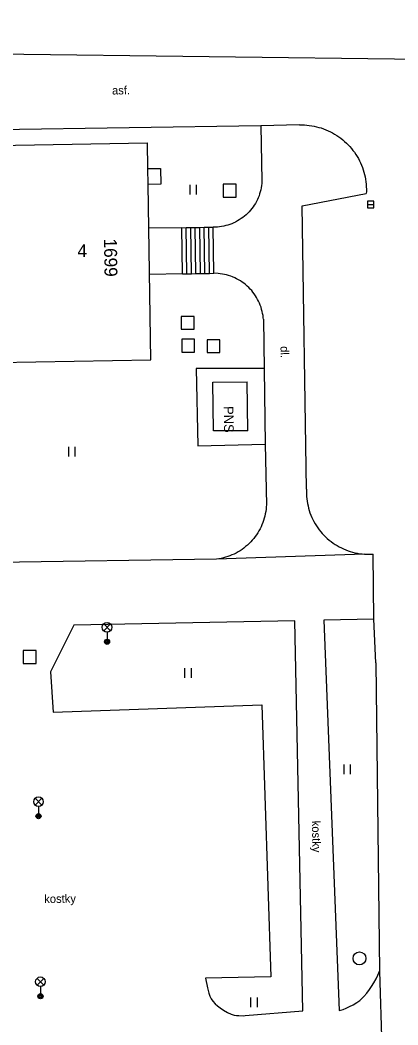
# Model space of a CAD drawing. Extents: x -641829 to -641525, y -1114855 to -1114359.
# Drawn here: x -641611.8 to -641582.5, y -1114437 to -1114358.9 of the extents above; entities that cross this region are included whole.
import ezdxf

# ---------------------------------------------------------------- set-up
doc = ezdxf.new("R2010")
doc.units = 0
for name, color, linetype in [('Vrstva 1', 7, 'Continuous'), ('Vrstva 10', 7, 'Continuous'), ('Vrstva 11', 7, 'Continuous'), ('Vrstva 24', 7, 'Continuous'), ('Vrstva 26', 7, 'Continuous'), ('Vrstva 27', 7, 'Continuous'), ('Vrstva 33', 7, 'Continuous'), ('Vrstva 36', 7, 'Continuous'), ('Vrstva 40', 7, 'Continuous'), ('Vrstva 41', 7, 'Continuous'), ('Vrstva 46', 7, 'Continuous'), ('Vrstva 47', 7, 'Continuous'), ('Vrstva 5', 7, 'Continuous')]:
    doc.layers.add(name, color=color, linetype=linetype)

msp = doc.modelspace()

# ---------------------------------------------------------------- linework, layer by layer
at = {"layer": 'Vrstva 1'}
msp.add_line((-641525.3, -1114362.64), (-641828.67, -1114358.89), dxfattribs=at)
at = {"layer": 'Vrstva 10'}
for p, q in [((-641593.11, -1114367.12), (-641618.09, -1114367.49)), ((-641590.1, -1114367.04), (-641593.11, -1114367.12)), ((-641590.1, -1114367.04), (-641589.91, -1114367.04)), ((-641589.91, -1114367.04), (-641589.72, -1114367.04)), ((-641589.72, -1114367.04), (-641589.53, -1114367.06)), ((-641589.53, -1114367.06), (-641589.34, -1114367.08)), ((-641589.34, -1114367.08), (-641589.15, -1114367.11)), ((-641589.15, -1114367.11), (-641588.96, -1114367.14)), ((-641588.96, -1114367.14), (-641588.78, -1114367.18)), ((-641588.78, -1114367.18), (-641588.59, -1114367.23)), ((-641588.59, -1114367.23), (-641588.41, -1114367.28)), ((-641588.41, -1114367.28), (-641588.23, -1114367.35)), ((-641588.23, -1114367.35), (-641588.05, -1114367.42)), ((-641588.05, -1114367.42), (-641587.87, -1114367.49)), ((-641587.87, -1114367.49), (-641587.7, -1114367.57)), ((-641587.7, -1114367.57), (-641587.53, -1114367.66)), ((-641587.53, -1114367.66), (-641587.37, -1114367.76)), ((-641587.37, -1114367.76), (-641587.2, -1114367.86)), ((-641587.2, -1114367.86), (-641587.05, -1114367.97)), ((-641587.05, -1114367.97), (-641586.89, -1114368.08)), ((-641586.89, -1114368.08), (-641586.74, -1114368.2)), ((-641586.74, -1114368.2), (-641586.6, -1114368.32)), ((-641586.6, -1114368.32), (-641586.46, -1114368.45)), ((-641586.46, -1114368.45), (-641586.32, -1114368.59)), ((-641586.32, -1114368.59), (-641586.19, -1114368.73)), ((-641586.19, -1114368.73), (-641586.07, -1114368.87)), ((-641586.07, -1114368.87), (-641585.95, -1114369.02)), ((-641585.95, -1114369.02), (-641585.84, -1114369.17)), ((-641585.84, -1114369.17), (-641585.73, -1114369.33)), ((-641585.73, -1114369.33), (-641585.63, -1114369.49)), ((-641585.63, -1114369.49), (-641585.53, -1114369.66)), ((-641585.53, -1114369.66), (-641585.44, -1114369.83)), ((-641585.44, -1114369.83), (-641585.36, -1114370)), ((-641585.36, -1114370), (-641585.28, -1114370.18)), ((-641585.28, -1114370.18), (-641585.21, -1114370.35)), ((-641585.21, -1114370.35), (-641585.15, -1114370.53)), ((-641585.15, -1114370.53), (-641585.1, -1114370.72)), ((-641585.1, -1114370.72), (-641585.05, -1114370.9)), ((-641585.05, -1114370.9), (-641585.01, -1114371.09)), ((-641585.01, -1114371.09), (-641584.97, -1114371.27)), ((-641584.97, -1114371.27), (-641584.94, -1114371.46)), ((-641584.94, -1114371.46), (-641584.92, -1114371.65)), ((-641584.92, -1114371.65), (-641584.91, -1114371.85)), ((-641584.91, -1114371.85), (-641584.9, -1114372.04)), ((-641584.9, -1114372.04), (-641584.9, -1114372.23)), ((-641589.89, -1114373.33), (-641584.91, -1114372.38)), ((-641584.9, -1114372.23), (-641584.91, -1114372.38)), ((-641589.57, -1114395.37), (-641589.89, -1114373.33)), ((-641589.57, -1114395.37), (-641589.57, -1114395.56)), ((-641589.57, -1114395.56), (-641589.57, -1114395.74)), ((-641589.57, -1114395.74), (-641589.56, -1114395.93)), ((-641589.56, -1114395.93), (-641589.54, -1114396.12)), ((-641589.54, -1114396.12), (-641589.52, -1114396.3)), ((-641589.52, -1114396.3), (-641589.49, -1114396.49)), ((-641589.49, -1114396.49), (-641589.44, -1114396.67)), ((-641589.44, -1114396.67), (-641589.4, -1114396.85)), ((-641589.4, -1114396.85), (-641589.35, -1114397.03)), ((-641589.35, -1114397.03), (-641589.29, -1114397.21)), ((-641589.29, -1114397.21), (-641589.22, -1114397.38)), ((-641589.22, -1114397.38), (-641589.15, -1114397.56)), ((-641589.15, -1114397.56), (-641589.07, -1114397.73)), ((-641589.07, -1114397.73), (-641588.98, -1114397.89)), ((-641588.98, -1114397.89), (-641588.89, -1114398.05)), ((-641588.89, -1114398.05), (-641588.79, -1114398.21)), ((-641588.79, -1114398.21), (-641588.68, -1114398.37)), ((-641588.68, -1114398.37), (-641588.57, -1114398.52)), ((-641588.57, -1114398.52), (-641588.45, -1114398.67)), ((-641588.45, -1114398.67), (-641588.33, -1114398.81)), ((-641588.33, -1114398.81), (-641588.2, -1114398.95)), ((-641588.2, -1114398.95), (-641588.07, -1114399.08)), ((-641588.07, -1114399.08), (-641587.94, -1114399.2)), ((-641587.94, -1114399.2), (-641587.79, -1114399.33)), ((-641587.79, -1114399.33), (-641587.65, -1114399.44)), ((-641587.65, -1114399.44), (-641587.49, -1114399.55)), ((-641587.49, -1114399.55), (-641587.34, -1114399.66)), ((-641587.34, -1114399.66), (-641587.18, -1114399.75)), ((-641587.18, -1114399.75), (-641587.02, -1114399.85)), ((-641587.02, -1114399.85), (-641586.85, -1114399.93)), ((-641586.85, -1114399.93), (-641586.68, -1114400.01)), ((-641586.68, -1114400.01), (-641586.51, -1114400.08)), ((-641586.51, -1114400.08), (-641586.33, -1114400.15)), ((-641586.33, -1114400.15), (-641586.16, -1114400.21)), ((-641586.16, -1114400.21), (-641585.98, -1114400.26)), ((-641585.98, -1114400.26), (-641585.79, -1114400.31)), ((-641585.79, -1114400.31), (-641585.61, -1114400.35)), ((-641585.61, -1114400.35), (-641585.43, -1114400.38)), ((-641585.43, -1114400.38), (-641585.24, -1114400.4)), ((-641585.24, -1114400.4), (-641585.05, -1114400.42)), ((-641585.05, -1114400.42), (-641584.87, -1114400.43)), ((-641584.87, -1114400.43), (-641584.68, -1114400.43)), ((-641584.68, -1114400.43), (-641584.49, -1114400.43)), ((-641584.49, -1114400.43), (-641584.39, -1114400.42)), ((-641584.33, -1114405.48), (-641584.39, -1114400.42)), ((-641584.18, -1114408.87), (-641584.33, -1114405.48)), ((-641584.18, -1114408.87), (-641583.89, -1114432.83)), ((-641583.89, -1114432.83), (-641583.53, -1114444.1))]:
    msp.add_line(p, q, dxfattribs=at)
at = {"layer": 'Vrstva 11'}
for p, q in [((-641593.11, -1114367.12), (-641593.02, -1114371.39)), ((-641593.11, -1114372.08), (-641593.15, -1114372.24)), ((-641593.08, -1114371.92), (-641593.11, -1114372.08)), ((-641593.05, -1114371.76), (-641593.08, -1114371.92)), ((-641593.03, -1114371.59), (-641593.05, -1114371.76)), ((-641593.02, -1114371.39), (-641593.03, -1114371.59)), ((-641593.38, -1114372.85), (-641593.45, -1114373)), ((-641593.31, -1114372.7), (-641593.38, -1114372.85)), ((-641593.25, -1114372.55), (-641593.31, -1114372.7)), ((-641593.2, -1114372.4), (-641593.25, -1114372.55)), ((-641593.15, -1114372.24), (-641593.2, -1114372.4)), ((-641593.81, -1114373.55), (-641593.91, -1114373.68)), ((-641593.71, -1114373.42), (-641593.81, -1114373.55)), ((-641593.62, -1114373.28), (-641593.71, -1114373.42)), ((-641593.53, -1114373.14), (-641593.62, -1114373.28)), ((-641593.45, -1114373), (-641593.53, -1114373.14)), ((-641594.78, -1114374.42), (-641594.92, -1114374.51)), ((-641594.64, -1114374.33), (-641594.78, -1114374.42)), ((-641594.51, -1114374.24), (-641594.64, -1114374.33)), ((-641594.38, -1114374.14), (-641594.51, -1114374.24)), ((-641594.26, -1114374.03), (-641594.38, -1114374.14)), ((-641594.14, -1114373.92), (-641594.26, -1114374.03)), ((-641594.02, -1114373.8), (-641594.14, -1114373.92)), ((-641593.91, -1114373.68), (-641594.02, -1114373.8)), ((-641599.26, -1114375.03), (-641601.82, -1114375.07)), ((-641599.26, -1114375.03), (-641598.91, -1114375.02)), ((-641599.2, -1114378.62), (-641599.26, -1114375.03)), ((-641598.85, -1114378.61), (-641598.91, -1114375.02)), ((-641598.91, -1114375.02), (-641598.56, -1114375.02)), ((-641598.56, -1114375.02), (-641598.21, -1114375.01)), ((-641598.5, -1114378.61), (-641598.56, -1114375.02)), ((-641598.15, -1114378.6), (-641598.21, -1114375.01)), ((-641598.21, -1114375.01), (-641597.86, -1114375.01)), ((-641597.86, -1114375.01), (-641597.51, -1114375)), ((-641597.8, -1114378.6), (-641597.86, -1114375.01)), ((-641597.45, -1114378.59), (-641597.51, -1114375)), ((-641597.51, -1114375), (-641597.16, -1114375)), ((-641597.16, -1114375), (-641596.81, -1114374.99)), ((-641597.1, -1114378.59), (-641597.16, -1114375)), ((-641596.48, -1114374.98), (-641596.81, -1114374.99)), ((-641596.76, -1114378.58), (-641596.81, -1114374.99)), ((-641596.32, -1114374.96), (-641596.48, -1114374.98)), ((-641596.16, -1114374.94), (-641596.32, -1114374.96)), ((-641595.99, -1114374.91), (-641596.16, -1114374.94)), ((-641595.84, -1114374.87), (-641595.99, -1114374.91)), ((-641595.68, -1114374.83), (-641595.84, -1114374.87)), ((-641595.52, -1114374.78), (-641595.68, -1114374.83)), ((-641595.37, -1114374.72), (-641595.52, -1114374.78)), ((-641595.22, -1114374.66), (-641595.37, -1114374.72)), ((-641595.07, -1114374.59), (-641595.22, -1114374.66)), ((-641594.92, -1114374.51), (-641595.07, -1114374.59)), ((-641599.2, -1114378.62), (-641601.76, -1114378.66)), ((-641599.2, -1114378.62), (-641598.85, -1114378.61)), ((-641598.85, -1114378.61), (-641598.5, -1114378.61)), ((-641598.5, -1114378.61), (-641598.15, -1114378.6)), ((-641598.15, -1114378.6), (-641597.8, -1114378.6)), ((-641597.8, -1114378.6), (-641597.45, -1114378.59)), ((-641597.45, -1114378.59), (-641597.1, -1114378.59)), ((-641597.1, -1114378.59), (-641596.76, -1114378.58)), ((-641596.42, -1114378.59), (-641596.76, -1114378.58)), ((-641596.26, -1114378.61), (-641596.42, -1114378.59)), ((-641596.09, -1114378.64), (-641596.26, -1114378.61)), ((-641595.93, -1114378.67), (-641596.09, -1114378.64)), ((-641595.77, -1114378.71), (-641595.93, -1114378.67)), ((-641595.61, -1114378.75), (-641595.77, -1114378.71)), ((-641595.45, -1114378.8), (-641595.61, -1114378.75)), ((-641595.3, -1114378.86), (-641595.45, -1114378.8)), ((-641595.14, -1114378.93), (-641595.3, -1114378.86)), ((-641594.99, -1114379), (-641595.14, -1114378.93)), ((-641594.85, -1114379.08), (-641594.99, -1114379)), ((-641594.7, -1114379.17), (-641594.85, -1114379.08)), ((-641594.56, -1114379.26), (-641594.7, -1114379.17)), ((-641594.43, -1114379.35), (-641594.56, -1114379.26)), ((-641594.3, -1114379.46), (-641594.43, -1114379.35)), ((-641594.17, -1114379.57), (-641594.3, -1114379.46)), ((-641594.05, -1114379.68), (-641594.17, -1114379.57)), ((-641593.94, -1114379.8), (-641594.05, -1114379.68)), ((-641593.82, -1114379.92), (-641593.94, -1114379.8)), ((-641593.72, -1114380.05), (-641593.82, -1114379.92)), ((-641593.62, -1114380.18), (-641593.72, -1114380.05)), ((-641593.53, -1114380.32), (-641593.62, -1114380.18)), ((-641593.44, -1114380.46), (-641593.53, -1114380.32)), ((-641593.36, -1114380.61), (-641593.44, -1114380.46)), ((-641593.28, -1114380.75), (-641593.36, -1114380.61)), ((-641593.21, -1114380.91), (-641593.28, -1114380.75)), ((-641593.15, -1114381.06), (-641593.21, -1114380.91)), ((-641593.09, -1114381.22), (-641593.15, -1114381.06)), ((-641593.05, -1114381.38), (-641593.09, -1114381.22)), ((-641593, -1114381.54), (-641593.05, -1114381.38)), ((-641592.97, -1114381.7), (-641593, -1114381.54)), ((-641592.94, -1114381.86), (-641592.97, -1114381.7)), ((-641592.92, -1114382.03), (-641592.94, -1114381.86)), ((-641592.91, -1114382.14), (-641592.92, -1114382.03)), ((-641598.13, -1114385.98), (-641598, -1114392)), ((-641592.85, -1114385.99), (-641598.13, -1114385.98)), ((-641598, -1114392), (-641592.76, -1114391.86)), ((-641592.7, -1114396.92), (-641592.73, -1114397.1)), ((-641592.69, -1114396.74), (-641592.7, -1114396.92)), ((-641592.68, -1114396.59), (-641592.69, -1114396.74)), ((-641592.9, -1114397.79), (-641592.95, -1114397.96)), ((-641592.84, -1114397.62), (-641592.9, -1114397.79)), ((-641592.8, -1114397.45), (-641592.84, -1114397.62)), ((-641592.76, -1114397.27), (-641592.8, -1114397.45)), ((-641592.73, -1114397.1), (-641592.76, -1114397.27)), ((-641593.26, -1114398.61), (-641593.35, -1114398.76)), ((-641593.17, -1114398.45), (-641593.26, -1114398.61)), ((-641593.09, -1114398.29), (-641593.17, -1114398.45)), ((-641593.02, -1114398.13), (-641593.09, -1114398.29)), ((-641592.95, -1114397.96), (-641593.02, -1114398.13)), ((-641593.77, -1114399.33), (-641593.89, -1114399.46)), ((-641593.66, -1114399.2), (-641593.77, -1114399.33)), ((-641593.55, -1114399.05), (-641593.66, -1114399.2)), ((-641593.45, -1114398.91), (-641593.55, -1114399.05)), ((-641593.35, -1114398.76), (-641593.45, -1114398.91)), ((-641594.72, -1114400.15), (-641594.87, -1114400.24)), ((-641594.57, -1114400.05), (-641594.72, -1114400.15)), ((-641594.43, -1114399.94), (-641594.57, -1114400.05)), ((-641594.29, -1114399.83), (-641594.43, -1114399.94)), ((-641594.15, -1114399.71), (-641594.29, -1114399.83)), ((-641594.02, -1114399.59), (-641594.15, -1114399.71)), ((-641593.89, -1114399.46), (-641594.02, -1114399.59)), ((-641596.55, -1114400.81), (-641616.13, -1114401.11)), ((-641585.05, -1114400.42), (-641596.55, -1114400.81)), ((-641596.37, -1114400.78), (-641596.55, -1114400.81)), ((-641596.2, -1114400.75), (-641596.37, -1114400.78)), ((-641596.02, -1114400.71), (-641596.2, -1114400.75)), ((-641595.85, -1114400.66), (-641596.02, -1114400.71)), ((-641595.68, -1114400.61), (-641595.85, -1114400.66)), ((-641595.51, -1114400.55), (-641595.68, -1114400.61)), ((-641595.35, -1114400.48), (-641595.51, -1114400.55)), ((-641595.19, -1114400.41), (-641595.35, -1114400.48)), ((-641595.03, -1114400.33), (-641595.19, -1114400.41)), ((-641594.87, -1114400.24), (-641595.03, -1114400.33)), ((-641590.47, -1114405.6), (-641607.64, -1114405.93)), ((-641589.84, -1114435.92), (-641590.47, -1114405.6)), ((-641584.33, -1114405.48), (-641588.2, -1114405.56)), ((-641588.2, -1114405.56), (-641587.01, -1114435.89)), ((-641607.64, -1114405.93), (-641609.45, -1114409.57)), ((-641609.45, -1114409.57), (-641609.26, -1114412.71)), ((-641609.26, -1114412.71), (-641593.04, -1114412.14)), ((-641593.04, -1114412.14), (-641592.34, -1114433.27)), ((-641592.34, -1114433.27), (-641597.42, -1114433.38))]:
    msp.add_line(p, q, dxfattribs=at)
for points in [[(-641592.91, -1114382.14), (-641592.76, -1114391.86), (-641592.68, -1114396.59)], [(-641585.28, -1114435), (-641585.09, -1114434.81), (-641584.87, -1114434.55), (-641584.66, -1114434.28), (-641584.5, -1114434.03), (-641584.32, -1114433.75), (-641584.15, -1114433.43), (-641584.01, -1114433.15), (-641583.89, -1114432.83)], [(-641597.42, -1114433.38), (-641597.25, -1114434.13), (-641597.15, -1114434.56), (-641597.06, -1114434.78), (-641596.96, -1114434.99)], [(-641596.96, -1114434.99), (-641596.83, -1114435.18), (-641596.67, -1114435.38), (-641596.47, -1114435.55), (-641596.27, -1114435.69), (-641596, -1114435.88), (-641595.7, -1114436.05), (-641595.41, -1114436.19), (-641595.18, -1114436.26)], [(-641587.01, -1114435.89), (-641586.7, -1114435.81), (-641586.47, -1114435.73), (-641586.21, -1114435.6), (-641585.93, -1114435.46), (-641585.65, -1114435.28), (-641585.42, -1114435.12), (-641585.28, -1114435)], [(-641595.18, -1114436.26), (-641594.99, -1114436.3), (-641594.82, -1114436.3), (-641594.45, -1114436.31), (-641594.33, -1114436.3), (-641589.84, -1114435.92)]]:
    msp.add_lwpolyline(points, dxfattribs=at)
at = {"layer": 'Vrstva 24'}
msp.add_lwpolyline([(-641601.89, -1114370.44), (-641600.91, -1114370.42), (-641600.89, -1114371.66), (-641601.87, -1114371.68), (-641601.89, -1114370.44)], dxfattribs=at)
at = {"layer": 'Vrstva 26'}
for points in [[(-641595.03, -1114371.66), (-641596.03, -1114371.66), (-641596.03, -1114372.66), (-641595.03, -1114372.66)], [(-641598.3, -1114381.93), (-641599.3, -1114381.93), (-641599.3, -1114382.93), (-641598.3, -1114382.93)], [(-641598.26, -1114383.71), (-641599.26, -1114383.71), (-641599.26, -1114384.71), (-641598.26, -1114384.71)], [(-641596.29, -1114383.74), (-641597.29, -1114383.74), (-641597.29, -1114384.74), (-641596.29, -1114384.74)], [(-641610.58, -1114407.92), (-641611.58, -1114407.92), (-641611.58, -1114408.92), (-641610.58, -1114408.92)]]:
    msp.add_lwpolyline(points, close=True, dxfattribs=at)
at = {"layer": 'Vrstva 27'}
msp.add_line((-641584.82, -1114373.23), (-641584.32, -1114373.23), dxfattribs=at)
msp.add_lwpolyline([(-641584.82, -1114373.48), (-641584.32, -1114373.48), (-641584.32, -1114372.98), (-641584.82, -1114372.98)], close=True, dxfattribs=at)
msp.add_circle((-641585.44, -1114431.85), 0.5, dxfattribs=at)
at = {"layer": 'Vrstva 33'}
for p, q in [((-641605.324, -1114406.37), (-641604.796, -1114405.84)), ((-641605.324, -1114405.84), (-641604.796, -1114406.37)), ((-641605.06, -1114406.48), (-641605.06, -1114407.23)), ((-641610.654, -1114419.93), (-641610.126, -1114419.4)), ((-641610.654, -1114419.4), (-641610.126, -1114419.93)), ((-641610.39, -1114420.04), (-641610.39, -1114420.79)), ((-641610.506, -1114433.93), (-641609.974, -1114433.4)), ((-641610.506, -1114433.4), (-641609.974, -1114433.93)), ((-641610.24, -1114434.04), (-641610.24, -1114434.79))]:
    msp.add_line(p, q, dxfattribs=at)
for centre, radius in [((-641605.06, -1114406.105), 0.375), ((-641605.06, -1114407.23), 0.2), ((-641605.06, -1114407.23), 0.145), ((-641605.06, -1114407.23), 0.0876), ((-641610.39, -1114419.665), 0.375), ((-641610.39, -1114420.79), 0.2), ((-641610.39, -1114420.79), 0.145), ((-641610.39, -1114420.79), 0.0876), ((-641610.24, -1114433.665), 0.375), ((-641610.24, -1114434.79), 0.2), ((-641610.24, -1114434.79), 0.145), ((-641610.24, -1114434.79), 0.0876)]:
    msp.add_circle(centre, radius, dxfattribs=at)
at = {"layer": 'Vrstva 36'}
for p, q in [((-641598.614, -1114372.444), (-641598.614, -1114371.692)), ((-641598.114, -1114372.444), (-641598.114, -1114371.692)), ((-641608.044, -1114392.834), (-641608.044, -1114392.082)), ((-641607.544, -1114392.834), (-641607.544, -1114392.082)), ((-641599.004, -1114410.022), (-641599.004, -1114409.274)), ((-641598.504, -1114410.022), (-641598.504, -1114409.274)), ((-641586.634, -1114417.522), (-641586.634, -1114416.774)), ((-641586.134, -1114417.522), (-641586.134, -1114416.774)), ((-641593.874, -1114435.632), (-641593.874, -1114434.884)), ((-641593.374, -1114435.632), (-641593.374, -1114434.884))]:
    msp.add_line(p, q, dxfattribs=at)
at = {"layer": 'Vrstva 5'}
for p, q in [((-641619.55, -1114385.61), (-641601.66, -1114385.31)), ((-641596.83, -1114387.04), (-641594.17, -1114387.03)), ((-641596.79, -1114390.83), (-641596.83, -1114387.04)), ((-641594.12, -1114390.82), (-641594.17, -1114387.03)), ((-641594.12, -1114390.82), (-641596.79, -1114390.83))]:
    msp.add_line(p, q, dxfattribs=at)
for points in [[(-641626.27, -1114368.85), (-641618.07, -1114368.71), (-641601.92, -1114368.43)], [(-641601.66, -1114385.31), (-641601.82, -1114375.07), (-641601.87, -1114371.68), (-641601.89, -1114370.44), (-641601.92, -1114368.43)]]:
    msp.add_lwpolyline(points, dxfattribs=at)

# ---------------------------------------------------------------- texts
at = {"layer": 'Vrstva 40'}
for s, rotation, p in [('asf.', 0.84404, (-641604.67, -1114364.68)), ('dl.', 270.83182, (-641591.58, -1114384.25)), ('kostky', 271.18845, (-641589.14, -1114421.15)), ('kostky', 0.89517, (-641609.94, -1114427.55))]:
    msp.add_text(s, height=0.65, rotation=rotation, dxfattribs=at).set_placement(p)
at = {"layer": 'Vrstva 41'}
msp.add_text('PNS', height=0.75, rotation=270.75584, dxfattribs=at).set_placement((-641595.99, -1114388.91))
at = {"layer": 'Vrstva 46'}
msp.add_text('4', height=1, dxfattribs=at).set_placement((-641607.36, -1114377.32))
at = {"layer": 'Vrstva 47'}
msp.add_text('1699', height=0.9999, rotation=270.88245, dxfattribs=at).set_placement((-641605.3, -1114375.88))

doc.saveas('drawing.dxf')
